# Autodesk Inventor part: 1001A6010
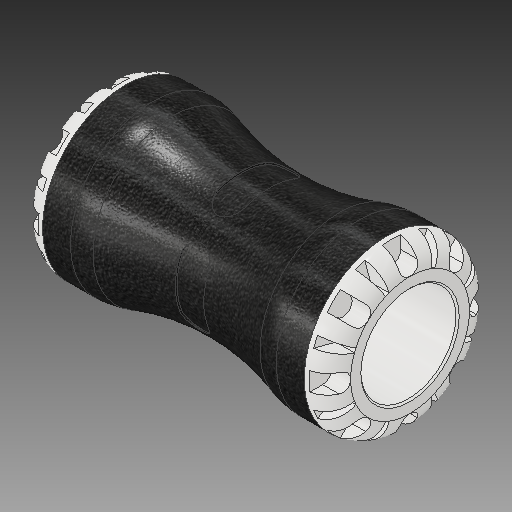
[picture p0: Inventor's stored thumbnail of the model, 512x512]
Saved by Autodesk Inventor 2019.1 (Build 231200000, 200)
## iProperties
Created: 2016-12
Part Number: 1001A6010
Material: PVC-Piping
Description: PLASSON COUPLER 1''IPS x 1''IPS SERIES 1
Document SubType Name: Modeling
Designer: KIM
Mass: 95.2094 g
Surface Area: 200.83 cm^2
Volume: 68.0067 cm^3
Density: 1.4 g/cm^3
Appearance: White
ILogicFactory: False
Author: KIM
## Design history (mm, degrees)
derived "1001A.ipt"
feature "Solid1::1001A.ipt"
tag "TaggingFeature1"
body "Solid1"
other parameters: "d2" = 53.848, "d4" = 2.775, "d11" = 6.5148, "d13" = 6.5148, "d14" = 0, "d16" = 360 deg, "d18" = 8 deg, "d19" = 0.666, "d20" = 8 deg, "d21" = 0.666, "d23" = 0, "d25" = 360 deg, "d27" = 23.1648, "d28" = 8.325, "d29" = 9.99, "d30" = 9.99, "d31" = 0, "d33" = 0, "d37" = 21.59, "d38" = 0.57912, "d43" = 4.1625, "d44" = 33.3, "d45" = 21.59, "d46" = 46.3296, "d47" = 57.912, "d48" = 107.95, "d50" = 360 deg, "d54" = 0.5, "d_" = 33.3, "E_" = 57.912, "H_" = 107.95, "l_" = 53.848, "d12" = 41.625, "d42" = 57.912, "d52" = 8.1435
